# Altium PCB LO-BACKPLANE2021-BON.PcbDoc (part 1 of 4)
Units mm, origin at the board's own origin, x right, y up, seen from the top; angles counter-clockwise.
Board outline 469.9 x 101.6 mm, 4 copper layers (1, Signal Layer 1, Signal Layer 2, 4), stack 1.53 mm thick; 160 components, 92 nets, 524 pads, 8354 vias.
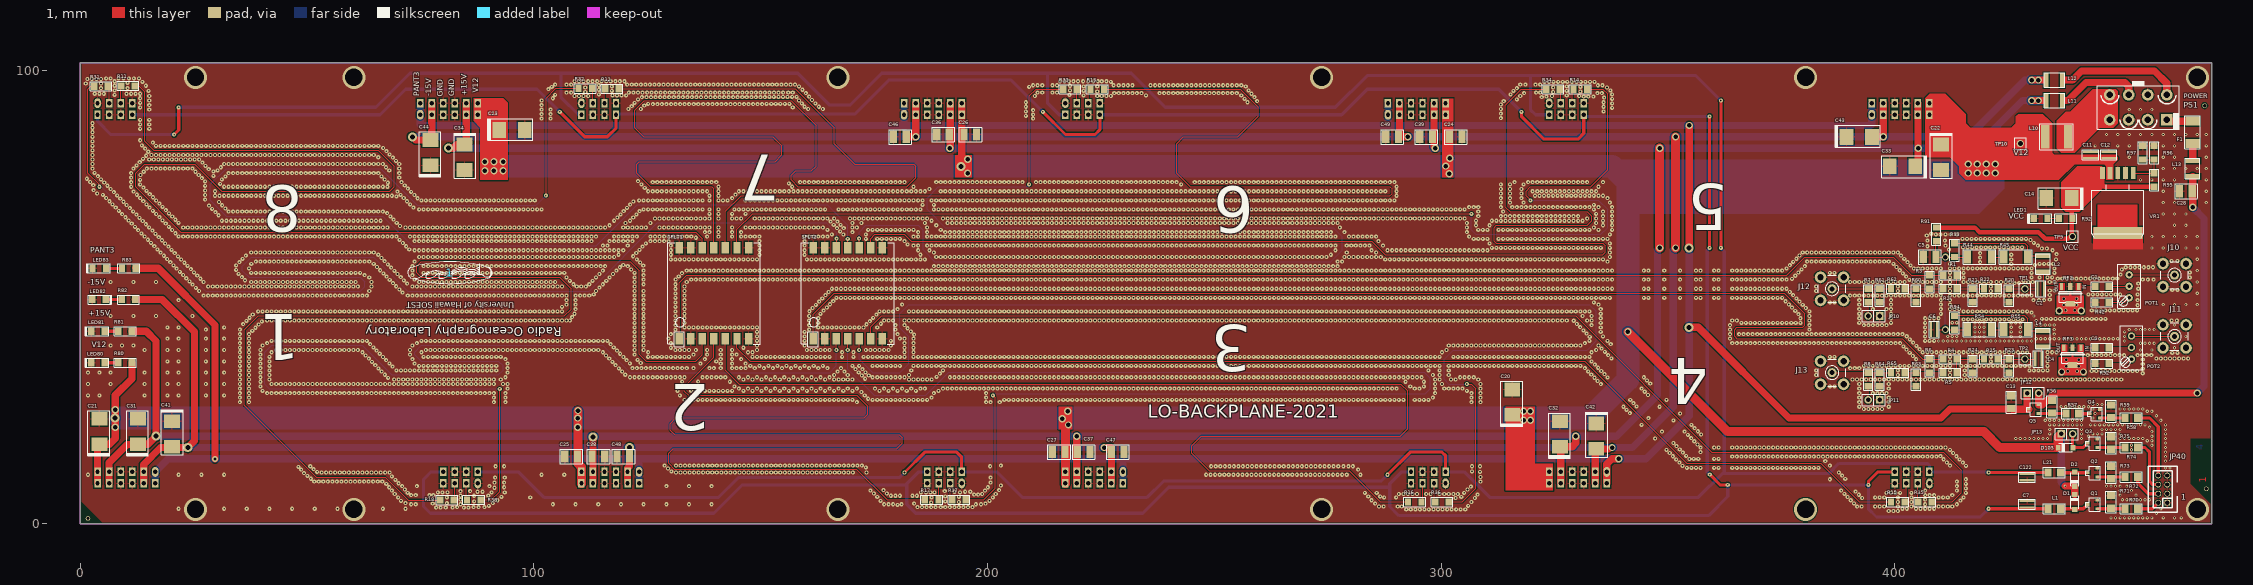
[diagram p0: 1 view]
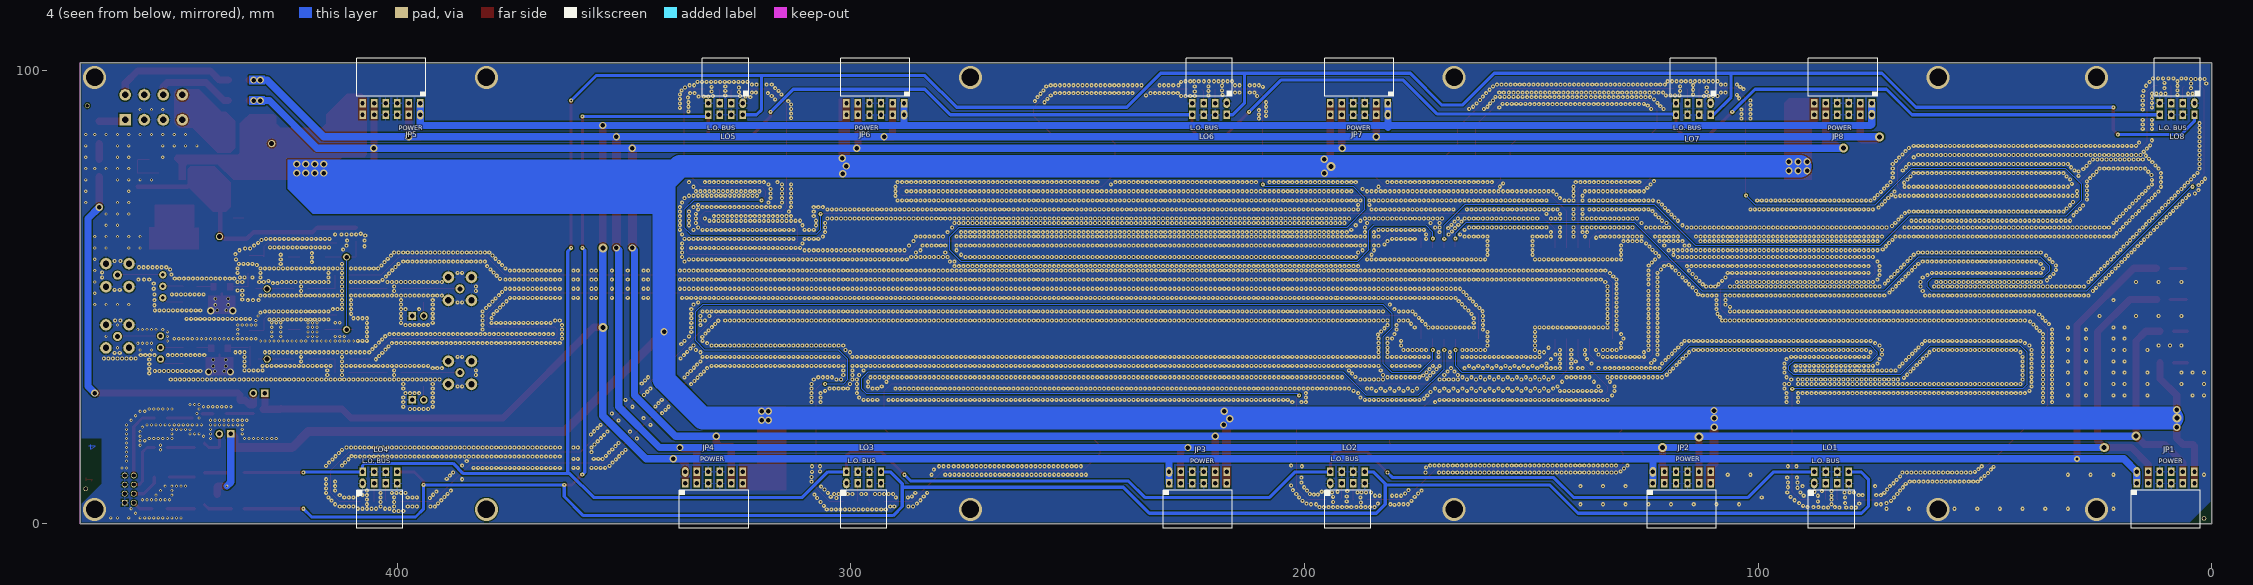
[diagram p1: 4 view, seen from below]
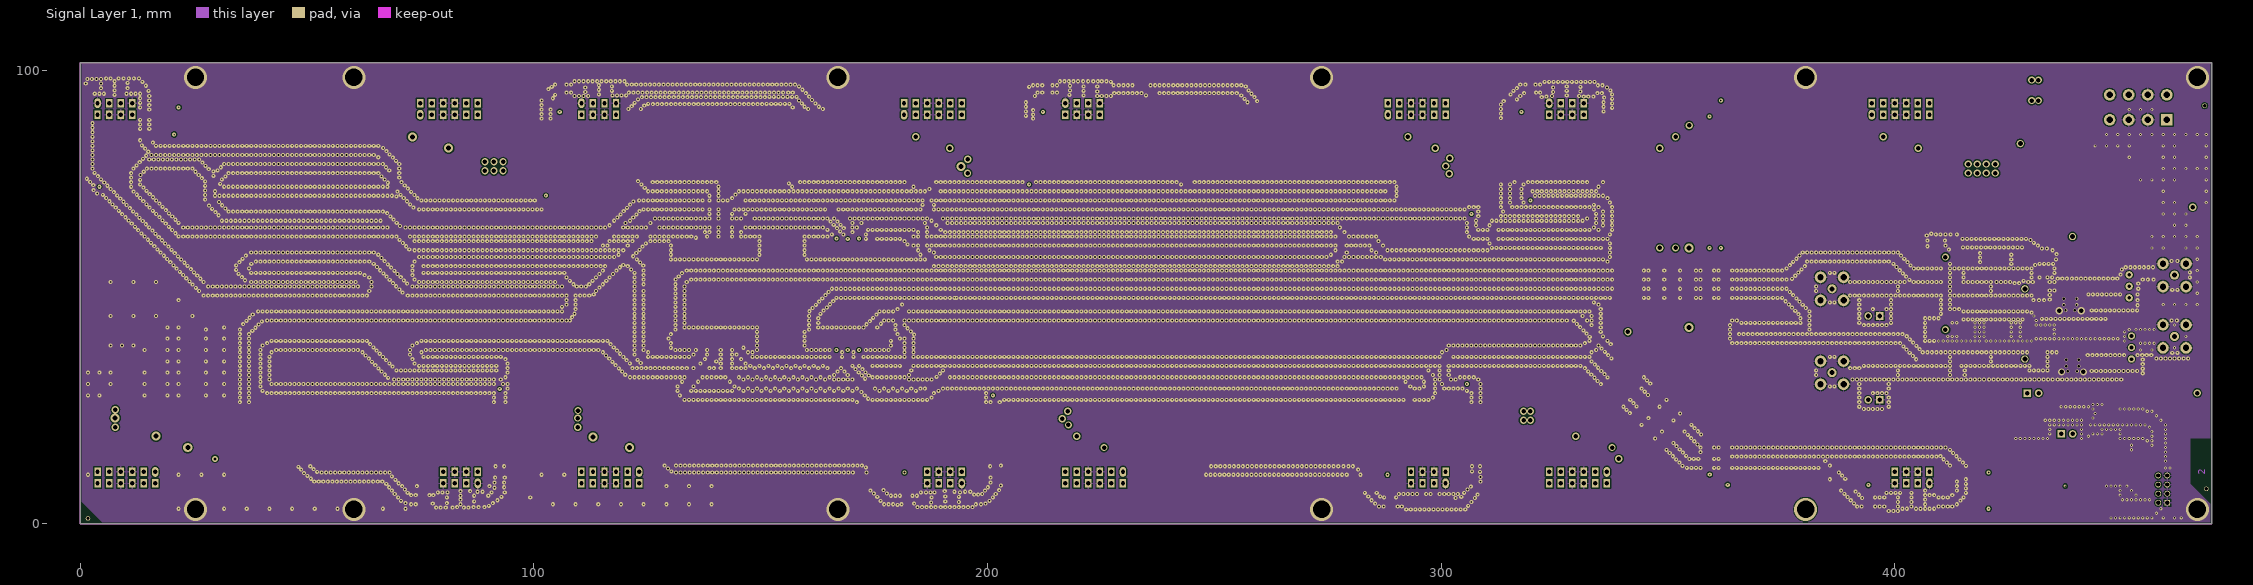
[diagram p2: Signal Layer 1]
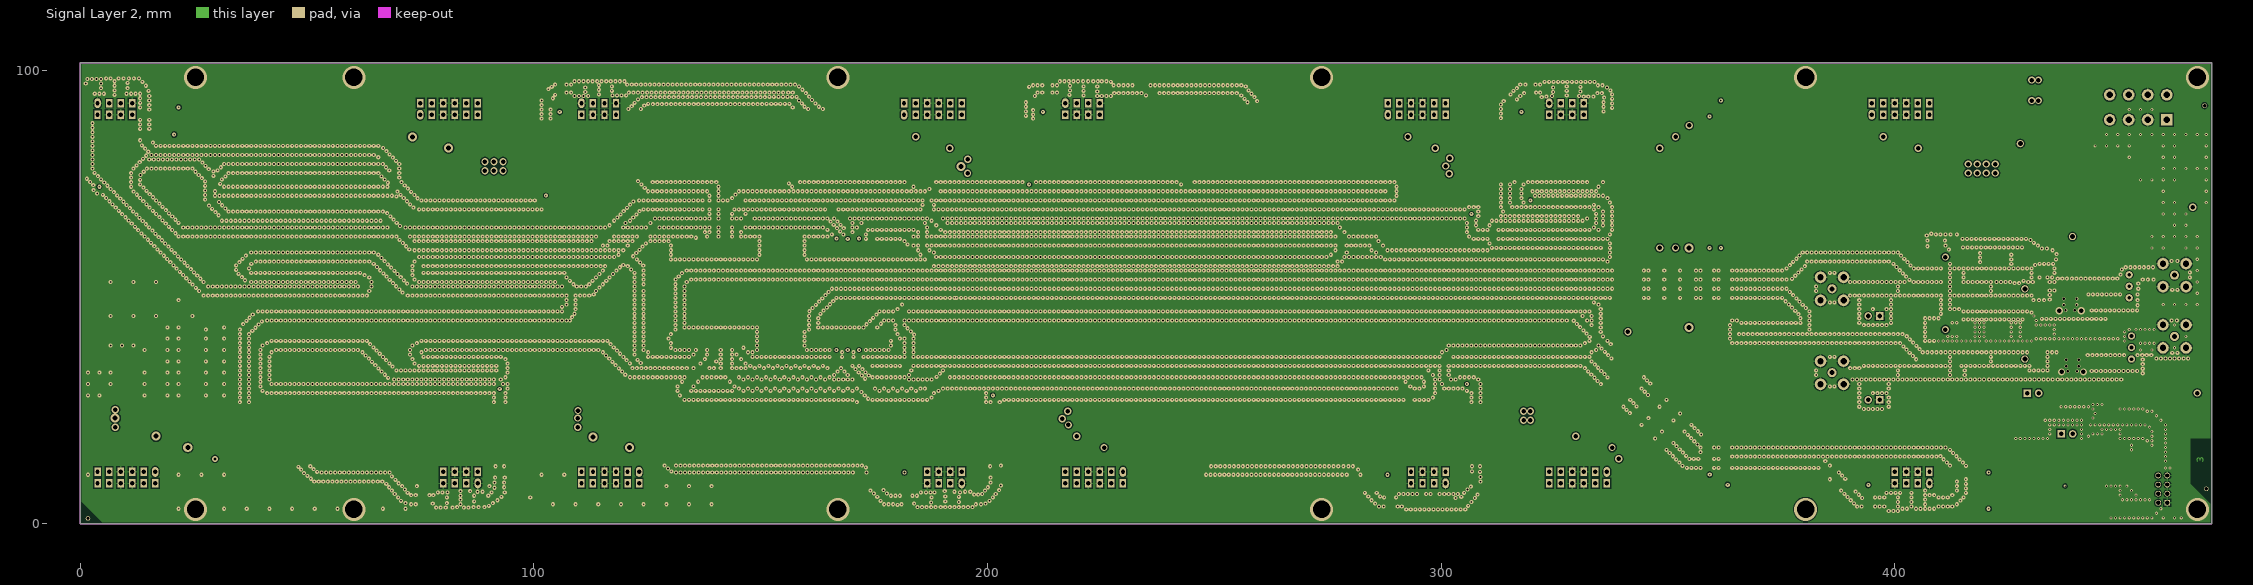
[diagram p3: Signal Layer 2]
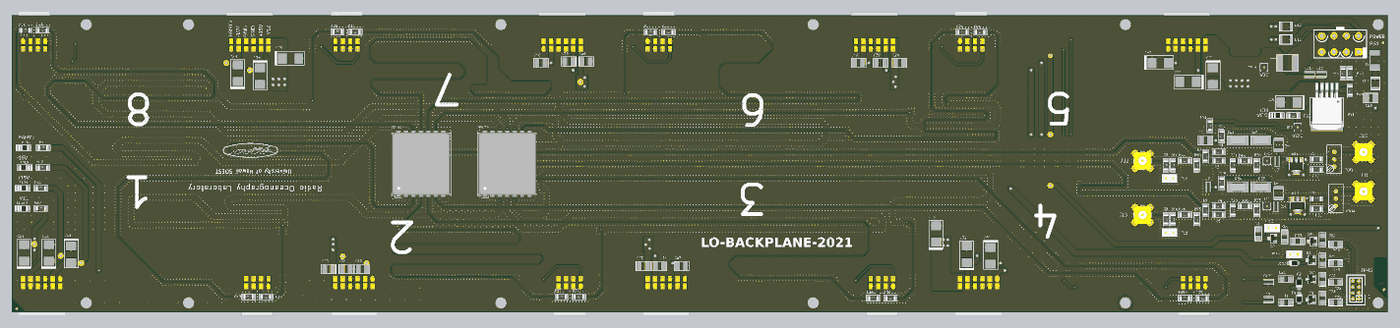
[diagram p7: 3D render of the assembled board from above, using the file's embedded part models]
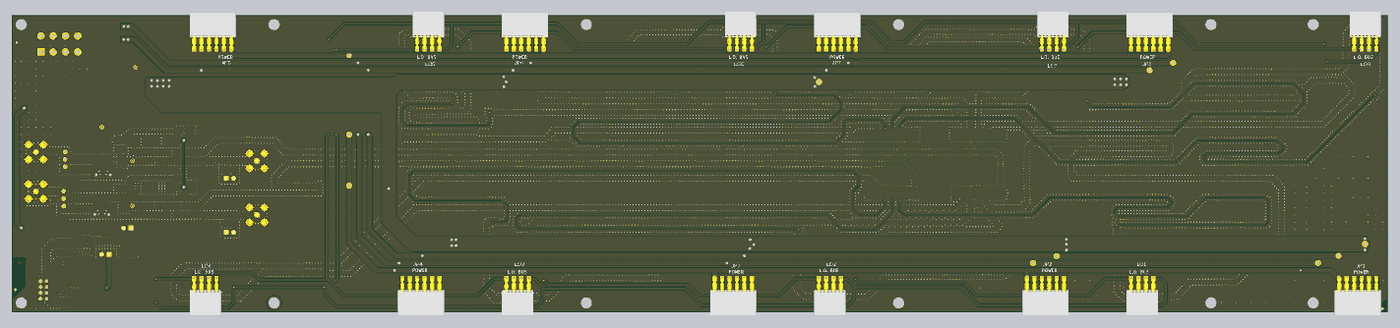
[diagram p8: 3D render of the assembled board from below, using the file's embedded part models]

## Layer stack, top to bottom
Top Solder: solder mask 0.02, Solder Resist, Dk 4
1: signal copper 0.035
Dielectric 1: prepreg 0.13, 2116, Dk 4.45
Signal Layer 1: signal copper 0.035
Dielectric 3: core 1.13, Dk 4.74
Signal Layer 2: signal copper 0.035
Dielectric 2: prepreg 0.13, 2116, Dk 4.45
4: signal copper 0.035
Bottom Solder: solder mask 0.02, Solder Resist, Dk 4

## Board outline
0,0 469.9,0 469.9,101.6 0,101.6

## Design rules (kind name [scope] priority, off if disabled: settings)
Clearance Clearance_6 [InNetClass('50R') vs InNet('GND')] p1: gap=0.18 ignorepadtopadclearanceinfootprint=FALSE
Clearance Clearance_5 [InNetClass('50R') vs InPolygon] p2 off: gap=0.18 ignorepadtopadclearanceinfootprint=FALSE
Clearance Clearance_4 [InNet('RF') vs InPolygon] p3 off: gap=0.55 ignorepadtopadclearanceinfootprint=FALSE
Clearance Clearance_2 [InNet('RF') vs InPolygon] p4 off: gap=0.55 ignorepadtopadclearanceinfootprint=FALSE
Clearance Clearance_3 [InNet('RF') vs InPolygon] p5 off: gap=0.55 ignorepadtopadclearanceinfootprint=FALSE
Clearance Clearance_1 [InPolygon] p6: gap=0.257 ignorepadtopadclearanceinfootprint=FALSE
Clearance [All] p7: gap=0.25 ignorepadtopadclearanceinfootprint=FALSE
ComponentClearance [All] p1 off: gap=0.254 collisioncheckmode=3 verticalgap=0.254 showdistances=FALSE
FabricationTestPointUsage TestPointUsage [All] p1: valid=0 allowmultiple=FALSE
FabricationTestpoint Testpoint [All] p1: side=3 testpointundercomponent=TRUE minsize=1.016 maxsize=2.54 preferedsize=1.524 minholesize=0.508 maxholesize=1.016 preferedholesize=0.813 testpointgrid=0.025 allowsidetop=TRUE allowsidebottom=TRUE usegrid=TRUE gridtolerance=0
HoleSize [All] p1: absolutevalues=TRUE maxlimit=10 minlimit=0.025 maxpercent=80.000 minpercent=20.000
HoleToHoleClearance [All] p1 off: gap=0.01 allowstackedmicrovias=TRUE
Length Length_entrées [InStructureClass('xSignals_entrées')] p1: maxlimit=333.1 minlimit=333
Length Length_sorties [InStructureClass('xSignals_sorties')] p2: maxlimit=274.8 minlimit=274.5
MatchedLengths MatchedLengths_xSignals_entrées [InxSignalClass('Xsignals_entrées')] p1: tolerance=0.2 checknetsindiffpair=FALSE checkdiffpairvsdiffpair=TRUE checkxsignals=TRUE checkothers=TRUE
MatchedLengths MatchedLengths_xSignals_sorties [InxSignalClass('Xsignals_sorties')] p2: tolerance=0.4 checknetsindiffpair=FALSE checkdiffpairvsdiffpair=TRUE checkxsignals=TRUE checkothers=TRUE
PlaneClearance PlaneClearance_15 [HasPad('TP88-TP')] p1 off: clearance=1.27
PlaneClearance PlaneClearance_16 [HasPad('TP85-TP')] p2 off: clearance=1.27
PlaneClearance PlaneClearance_13 [HasPad('TP86-TP')] p3 off: clearance=1.27
PlaneClearance PlaneClearance_14 [HasPad('TP84-TP')] p4 off: clearance=1.27
PlaneClearance PlaneClearance_17 [HasPad('TP81-TP')] p5 off: clearance=1.27
PlaneClearance PlaneClearance_20 [HasPad('TP99-TP')] p6 off: clearance=1.27
PlaneClearance PlaneClearance_21 [HasPad('TP83-TP')] p7 off: clearance=1.27
PlaneClearance PlaneClearance_18 [HasPad('TP87-TP')] p8 off: clearance=1.27
PlaneClearance PlaneClearance_19 [HasPad('TP82-TP')] p9 off: clearance=1.27
PlaneClearance PlaneClearance_4 [HasPad('TPQ3-TP')] p10 off: clearance=0.381
PlaneClearance PlaneClearance_5 [HasPad('TP8-TP')] p11 off: clearance=0.381
PlaneClearance PlaneClearance_6 [HasPad('TP14-TP')] p12 off: clearance=0.381
PlaneClearance PlaneClearance_1 [HasPad('TP3-TP')] p13 off: clearance=0.381
PlaneClearance PlaneClearance_2 [HasPad('TP2-TP')] p14 off: clearance=0.381
PlaneClearance PlaneClearance_3 [HasPad('TP1-TP')] p15 off: clearance=0.381
PlaneClearance PlaneClearance_10 [HasPad('TP5-TP')] p16 off: clearance=0.381
PlaneClearance PlaneClearance_11 [HasPad('TP12-TP')] p17 off: clearance=0.381
PlaneClearance PlaneClearance_12 [HasPad('TP108-TP')] p18 off: clearance=0.381
PlaneClearance PlaneClearance_7 [HasPad('TPQ14-TP')] p19 off: clearance=0.381
PlaneClearance PlaneClearance_8 [HasPad('TP9-TP')] p20 off: clearance=0.381
PlaneClearance PlaneClearance_9 [HasPad('TPQ5-TP')] p21 off: clearance=0.381
PlaneClearance [All] p22 off: clearance=0.254
PlaneConnect PlaneConnect_1 [All] p1 off: planeconnectstyle=Relief reliefexpansion=0.508 reliefentries=4 reliefconductorwidth=0.254 reliefairgap=0.254
PlaneConnect [All] p2 off: planeconnectstyle=Relief reliefexpansion=0.508 reliefentries=4 reliefconductorwidth=0.254 reliefairgap=0.254
PolygonConnect PolygonConnect_1 [IsVia] p1 off: connectstyle=Direct reliefconductorwidth=0.254 reliefentries=4 polygonreliefangle="90 Angle" airgapwidth=0.254
PolygonConnect PolygonConnect_2 [All] p2: thpad.connectstyle=Relief thpad.reliefconductorwidth=0.4 thpad.reliefentries=4 thpad.polygonreliefangle="90 Angle" thpad.airgapwidth=0.257 smdpad.connectstyle=Relief smdpad.reliefconductorwidth=0.4 smdpad.reliefentries=4 smdpad.polygonreliefangle="90 Angle" smdpad.airgapwidth=0.257 via.connectstyle=Direct via.reliefconductorwidth=0.254 via.reliefentries=4 via.polygonreliefangle="90 Angle" via.airgapwidth=0.254
PolygonConnect [All] p3 off: connectstyle=Relief reliefconductorwidth=0.254 reliefentries=4 polygonreliefangle="90 Angle" airgapwidth=0.257
RoutingPriority [All] p1: routingpriority=2
RoutingVias [All] p1: holewidth=0.3 width=0.7 viastyle="Through Hole" minholewidth=0.3 minwidth=0.7 maxholewidth=2 maxwidth=5
SilkToSilkClearance [All] p1 off: silktosilkclearance=0.254
SilkToSolderMaskClearance [IsPad] p1 off: minsilkscreentomaskgap=0.254 clearancetoexposedcopper=TRUE
SolderMaskExpansion [All] p1: expansion=0.051
UnpouredPolygon [All] p1 off:
Width Width_50R [InNetClass('50R')] p1: maxlimit=0.254 minlimit=0.185 preferedwidth=0.254 toplayer_maxwidth=0.185 toplayer_prefwidth=0.185 midlayer1_minwidth=0.254 midlayer2_minwidth=0.254 bottomlayer_maxwidth=0.185 bottomlayer_prefwidth=0.185 minimp=50.000000 maximp=50.000000 favimp=50.000000
Width [All] p2: maxlimit=10 minlimit=0.18 preferedwidth=0.635 midlayer1_minwidth=0.254 midlayer1_maxwidth=0.254 midlayer1_prefwidth=0.254 midlayer2_minwidth=0.254 midlayer2_maxwidth=0.254 midlayer2_prefwidth=0.254 minimp=50.000000 maximp=50.000000 favimp=50.000000
19 further rules are at their usual default settings.

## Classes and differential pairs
component class 1-BON: C11 C12 C14 C20 C21 C22 C23 C24 C25 C26 C27 C28 C31 C32 C33 C34 C36 C37 C38 C39 C41 C42 C43 C44 C46 C47 C48 C49 F1 JP1 JP2 JP3 JP4 JP5 JP6 JP7 JP8 L10 L11 L12 L13 LED1 LED80 LED81 LED82 LED83 PS1 R80 R81 R82 R83 R92 R95 R96 R97 TP9 TP10 VR1
component class 2-BON: AR1 C7 C13 C122 D1 D2 D103 JP12 JP13 JP40 L1 L21 LO1 LO2 LO3 LO4 LO5 LO6 LO7 LO8 Q1 Q2 Q3 Q4 Q5 R56 R57 R58 R59 R70 R71 R72 R73 R74 R75
component class 3-BON: C1 C2 C3 C4 C5 C6 J10 J11 J12 J13 JP10 JP11 L2 L4 POT1 POT2 R1 R2 R3 R4 R5 R6 R7 R8 R11 R12 R13 R14 R15 R16 R17 R18 R20 R21 R22 R23 R24 R25 R31 R32 R33 R34 R35 R36 R37 R38 R42 R44 R45 R52 R54 R55 R60 R61 R62 R63 R64 R65 R91 R93 R94 RF1 RF3 SPLT1 SPLT2 TP1 TP2
net class 50R: I1 I2 I3 I4 I5 I6 I7 I8 I-BUS LOI1+ LOI2 LOI3 LOI4 LOQ1+ LOQ2 LOQ3 LOQ4 NetJ12_1 NetJ13_1 NetJP10_2 NetJP11_2 NetPOT1_1 NetPOT2_1 NetR1_1 NetR1_2 NetR2_2 NetR4_1 NetR4_2 NetR5_2 NetR11_1 NetR12_1 NetR13_1 NetR14_1 NetR15_1 NetR16_1 NetR17_1 NetR18_1 NetR31_1 NetR32_1 NetR33_1 NetR34_1 NetR35_1 NetR36_1 NetR37_1 NetR38_1 Q1 Q2 Q3 Q4 Q5 Q6 Q7 Q8 Q-BUS

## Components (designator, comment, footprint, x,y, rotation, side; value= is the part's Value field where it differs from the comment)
1 "" LOGOTINY 81.495,55.361 r0 top
C1 "22nF NPO" C1206 445.7,52.3 r0 top
C2 "470nF" 0612 432.2,51.8 r90 top
C3 "22nF NPO" C1206 445.7,38.8 r0 top
C4 "470nF" 0612 431.7,36.3 r90 top
C5 "4.7uF" 1210 407.7,58.8 r180 top
C6 "470nF" 0612 408.7,42.8 r270 top
C7 "470nF" 0612 429.2,4.3 r180 top
C11 "470nF" 0612 443.2,81.3 r180 top
C12 "470nF" 0612 447.2,81.3 r180 top
C13 "4.7uF" 1206 425.7,26.8 r90 top
C14 "22uF 20V" 293D 436.2,71.8 r180 top
C20 "22uF 20V" 293D 315.7,26.8 r90 top
C21 "22uF 20V" 293D 4.2,20.3 r90 top
C22 "22uF 20V" 293D 410.2,80.8 r270 top
C23 "22uF 20V" 293D 95.2,86.8 r0 top
C24 "4.7uF" 1210 303.2,85.3 r0 top
C25 "4.7uF" 1210 108.2,14.8 r180 top
C26 "4.7uF" 1210 196.2,85.8 r0 top
C27 "4.7uF" 1210 215.7,15.8 r180 top
C28 "4.7uF" 1210 464.2,73.3 r180 top
C31 "22uF 20V" 293D 12.7,20.3 r90 top
C32 "22uF 20V" 293D 326.2,19.8 r90 top
C33 "22uF 20V" 293D 401.7,78.8 r180 top
C34 "22uF 20V" 293D 84.7,80.8 r270 top
C36 "4.7uF" 1210 190.2,85.8 r180 top
C37 "4.7uF" 1210 221.2,15.8 r0 top
C38 "4.7uF" 1210 114.2,14.8 r0 top
C39 "4.7uF" 1210 296.7,85.3 r180 top
C41 "22uF 20V" 293D 20.2,19.8 r270 top
C42 "22uF 20V" 293D 334.2,19.3 r270 top
C43 "22uF 20V" 293D 392.2,85.3 r0 top
C44 "22uF 20V" 293D 77.2,81.8 r90 top
C46 "4.7uF" 1210 180.7,85.3 r0 top
C47 "4.7uF" 1210 228.7,15.8 r180 top
C48 "4.7uF" 1210 119.7,14.8 r0 top
C49 "4.7uF" 1210 289.2,85.3 r0 top
C122 "470nF" 0612 429.2,10.3 r0 top
D1 "1N4148W" SOD123 439.7,4.8 r90 top
D2 "1N4148W" SOD123 439.7,9.8 r270 top
D103 "1N4148W" SOD123 437.7,16.8 r180 top
F1 "3A" "0452 (Littlefuse)" 465.7,86.3 r90 top
J10 "LO-I" MCX-J-P-H-ST-TH1 461.7,54.8 r0 top
J11 "LO-Q" MCX-J-P-H-ST-TH1 461.7,41.3 r0 top
J12 "LO-I" MCX-J-P-H-ST-TH1 386.2,51.8 r0 top
J13 "LO-Q" MCX-J-P-H-ST-TH1 386.2,33.3 r0 top
JP1 "POWER" SSW-106-02-G-D-RA 16.51,11.43 r0 bottom
JP2 "POWER" SSW-106-02-G-D-RA 123.19,11.43 r0 bottom
JP3 "POWER" SSW-106-02-G-D-RA 229.87,11.43 r0 bottom
JP4 "POWER" SSW-106-02-G-D-RA 336.55,11.43 r0 bottom
JP5 "POWER" SSW-106-02-G-D-RA 394.97,90.17 r180 bottom
JP6 "POWER" SSW-106-02-G-D-RA 288.29,90.17 r180 bottom
JP7 "POWER" SSW-106-02-G-D-RA 181.61,90.17 r180 bottom
JP8 "POWER" SSW-106-02-G-D-RA 74.93,90.17 r180 bottom
JP10 "" 2X2.54 396.7,45.8 r270 top
JP11 "" 2X2.54 396.7,27.3 r270 top
JP12 "" 2X2.54 429.2,28.8 r90 top
JP13 "" 2X2.54 436.7,19.8 r90 top
JP40 "RX ATTEN. CTRL" 2MM4X2SHRD 459.105,7.62 r90 top
L1 "Ferrite 1206" 1206 435.2,3.3 r0 top
L2 "4.7uH 1812" 1812 432.7,57.3 r90 top
L4 "4.7uH 1812" 1812 432.7,40.8 r90 top
L10 "Ferrite 2220" 2220 435.7,85.3 r0 top
L11 "Ferrite 1812" 1812 435.2,93.3 r0 top
L12 "Ferrite 1812" 1812 435.2,97.8 r0 top
L13 "Ferrite 1812" 1812 465.7,78.3 r90 top
L21 "Ferrite 1206" 1206 435.2,11.3 r0 top
LED1 "LO POWER" 1206D1 433.7,67.3 r180 top
LED80 "GALI-POWER" 1206D1 5.386,35.498 r180 top
LED81 "VA15+" 1206D1 5.386,42.428 r180 top
LED82 "VA15-" 1206D1 2.631,49.411 r0 top
LED83 "ACT-ANT" 1206D1 5.7,56.3 r180 top
LO1 "L.O. BUS" SSW-104-02-G-D-RA#1 87.63,11.43 r180 bottom
LO2 "L.O. BUS" SSW-104-02-G-D-RA#1 194.31,11.43 r180 bottom
LO3 "L.O. BUS" SSW-104-02-G-D-RA#1 300.99,11.43 r180 bottom
LO4 "L.O. BUS" SSW-104-02-G-D-RA#1 407.67,11.43 r180 bottom
LO5 "L.O. BUS" SSW-104-02-G-D-RA#1 323.85,90.17 r0 bottom
LO6 "L.O. BUS" SSW-104-02-G-D-RA#1 217.17,90.17 r0 bottom
LO7 "L.O. BUS" SSW-104-02-G-D-RA#1 110.49,90.17 r0 bottom
LO8 "L.O. BUS" SSW-104-02-G-D-RA#2 3.81,90.17 r0 bottom
POT1 "POT 50" t93ya 451.7,49.8 r90 top locked
POT2 "POT 50" t93ya 452.2,36.3 r90 top locked
PS1 "POWER" MFTJR2X4 453.7,91.8 r180 top
Q1 "MMBT2484LT1G" SOT23 444.7,3.3 r270 top
Q2 "MMBT2484LT1G" SOT23 444.7,10.3 r270 top
Q3 "MMBT2484LT1G" SOT23 444.7,16.8 r270 top
Q4 "MMBT2484LT1G" SOT23 445.2,23.3 r270 top
Q5 "PMV48XP,215" SOT23 431.7,24.3 r270 top
R1 "49.9" R1206 412.2,54.8 r180 top
R2 "49.9" R1206 412.2,51.8 r180 top
R3 "49.9" R1206 407.7,53.3 r270 top
R4 "49.9" R1206 412.2,36.3 r180 top
R5 "49.9" R1206 412.2,33.3 r180 top
R6 "49.9" R1206 407.7,34.8 r270 top
R7 "49.9" R1206 394.2,50.3 r270 top
R8 "49.9" R1206 394.2,31.8 r270 top
R11 "0" R1206 10.504,96.527 r180 top
R12 "0" R1206 117.244,95.881 r180 top
R13 "0" R1206 224.2,95.8 r180 top
R14 "0" R1206 330.7,95.8 r180 top
R15 "0" R1206 400.7,4.8 r0 top
R16 "0" R1206 294.2,4.8 r0 top
R17 "0" R1206 187.7,5.3 r0 top
R18 "0" R1206 80.869,5.23 r0 top
R20 "124" R1206 425.2,50.3 r270 top
R21 "124" R1206 417.2,50.3 r270 top
R22 "48.7" R1206 421.2,51.8 r180 top
R23 "124" R1206 425.2,34.8 r270 top
R24 "124" R1206 417.2,34.8 r270 top
R25 "48.7" R1206 421.2,36.3 r180 top
R31 "0" R1206 4.545,96.428 r0 top
R32 "0" R1206 111.335,95.956 r0 top
R33 "0" R1206 218.2,95.8 r0 top
R34 "0" R1206 324.7,95.8 r0 top
R35 "0" R1206 406.7,4.8 r180 top
R36 "0" R1206 300.2,4.8 r180 top
R37 "0" R1206 193.7,5.3 r180 top
R38 "0" R1206 86.754,5.255 r180 top
R42 "105" R1206 445.7,48.8 r180 top
R44 "20.5ohm" 2010-5x2.5 418.7,58.8 r0 top
R45 "20.5ohm" 2010-5x2.5 426.7,58.8 r0 top
R52 "105" R1206 445.7,35.3 r180 top
R54 "20.5ohm" 2010-5x2.5 418.7,42.8 r0 top
R55 "20.5ohm" 2010-5x2.5 426.7,42.8 r0 top
R56 "10k" 1206 434.7,25.8 r270 top
R57 "2K" 1206 439.2,24.3 r0 top
R58 "1k" 1206 452.2,23.3 r180 top
R59 "10k" 1206 447.7,24.8 r90 top
R60 "124" R1206 404.7,50.3 r270 top
R61 "124" R1206 396.7,50.3 r270 top
R62 "48.7" R1206 400.7,51.8 r180 top
R63 "124" R1206 404.7,31.8 r270 top
R64 "124" R1206 396.7,31.8 r270 top
R65 "48.7" R1206 400.7,33.3 r180 top
R70 "1k" 1206 452.2,3.3 r0 top
R71 "10k" 1206 447.7,4.8 r90 top
R72 "1k" 1206 452.2,10.3 r180 top
R73 "10k" 1206 447.7,11.3 r90 top
R74 "1k" 1206 452.2,16.8 r180 top
R75 "10k" 1206 447.7,17.8 r90 top
R80 "4.49k" R1206 9.886,35.498 r0 top
R81 "4.49k" R1206 9.886,42.428 r0 top
R82 "4.49k" R1206 10.631,49.411 r0 top
R83 "4.49k" R1206 10.7,56.3 r0 top
R91 "1R0" R1206 409.2,63.8 r270 top
R92 "4.49k" R1206 437.7,67.3 r180 top
R93 "0 DNI" R1206 413.2,60.3 r90 top
R94 "0 DNI" R1206 413.2,44.3 r90 top
R95 "1.8K" R1206 457.2,75.8 r90 top
R96 "249" R1206 457.2,81.8 r90 top
R97 "DNI" R1206 454.7,81.8 r90 top
RF1 "GALI-84" DF782 438.7,52.3 r180 top
RF3 "GALI-84" DF782 439.2,38.8 r180 top
SPLT1 "JCPS-8-10+" BG291 139.7,50.8 r0 top locked
SPLT2 "JCPS-8-10+" BG291 169.2,50.8 r0 top locked
TP1 "I-BUS" 61300111121 428.7,51.8 r0 top
TP2 "Q-BUS" 61300111121 428.7,36.3 r0 top
TP9 "+10.4V" 61300111121 439.2,63.3 r0 top
TP10 "+12V" 61300111121 427.7,83.8 r90 top
VR1 "LM2941S" TO263-5 449.2,77.3 r180 top

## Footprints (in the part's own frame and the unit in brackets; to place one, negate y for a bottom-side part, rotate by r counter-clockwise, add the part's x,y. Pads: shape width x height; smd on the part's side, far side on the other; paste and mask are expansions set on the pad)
2MM4X2SHRD [mm]
  rect 1.27x1.27 hole 0.914: 1(-3,-1)
  round 1.27 hole 0.914: 2(-3,1) 3(-1,-1) 4(-1,1) 5(1,-1) 6(1,1) 7(3,-1) 8(3,1)
  silkscreen extent -5.08,-3.18 5.08,3.18
2X2.54 [mm]
  rect 1.67x1.67 hole 1: 1(0,0)
  round 1.67 hole 1: 2(0,-2.54)
  silkscreen extent -1.27,-3.81 1.27,1.27, body extent -1.26,-3.8 1.28,1.28, height 9.54
293D [mm]
  rect 3x3.5 smd: +(-2.806,0) -(2.806,0)
  silkscreen extent -5.32,-2.3 4.59,2.51, body extent -3.69,-2.19 3.71,2.26, height 3.01
"0452 (Littlefuse)" [mm]
  rect 1.96x3.15 smd mask+0.05: 1(-2.45,0) 2(2.45,0)
  silkscreen extent -3.6,-1.7 3.6,1.7, body extent -3,-1.34 3,1.35, height 2.69
0612 [mm]
  rect 3.3x0.5 smd mask+0.1: 1(0,0.7) 2(0,-0.7)
  silkscreen extent -1.8,-1.1 1.8,1.1, body extent -1.6,-0.8 1.6,0.8, height 0.6
1206 [mm] "Chip Resistor; Body 3.2 x 1.6 mm (LxW typ)"
  rect 1.6x1.8 smd: 1(-1.4,0) 2(1.4,0)
  silkscreen extent -2.41,-1.14 2.41,1.14
1206D1 [mm]
  rect 1.4x1.6 smd: A(0,0) K(3,0)
  silkscreen extent -0.9,-1 4.32,1, body extent 0,-0.86 3.35,0.86, height 0.85
1210 [mm] "Chip Capacitor; Body 3.2 x 2.5 mm (LxW typ)"
  rect 1.6x2.7 smd: 1(-1.4,0) 2(1.4,0)
  silkscreen extent -2.5,-1.6 2.5,1.6
1812 [mm] "Chip Capacitor; Body 4.5 x 3.2 mm (LxW typ)"
  rect 1x3.2 smd: 1(-1.75,0) 2(1.75,0)
  silkscreen extent -2.25,-1.6 2.25,1.6
2010-5x2.5 [mm]
  rect 1.65x2.85 smd mask+0.1: 1(-2.65,0) 2(2.65,0)
  silkscreen extent -3.6,-1.6 3.6,1.6, body extent -2.5,-1.25 2.5,1.25, height 0.6
2220 [mm] "Chip Resistor; Body 5.7 x 5 mm (LxW typ)"
  rect 1.85x5.2 smd: 1(-2.525,0) 2(2.525,0)
  silkscreen extent -3.7,-2.85 3.7,2.85
61300111121 [mm] "1pins, 1 row, straight, gold plating"
  round 1.6 hole 1.1: 1(0,0)
  silkscreen extent -1.27,-1.27 1.27,1.27, body extent -1.27,-1.27 1.27,1.27, height 8.57
BG291 [mm]
  rect 1.65x2.54 smd mask+0.1: 1(-7.62,-10.035) 2(-5.08,-10.035) 3(-2.54,-10.035) 4(0,-10.035) 5(2.54,-10.035) 6(5.08,-10.035) 7(7.62,-10.035) 8(7.62,10.035) 9(5.08,10.035) 10(2.54,10.035) 11(0,10.035) 12(-2.54,10.035) 13(-5.08,10.035) 14(-7.62,10.035)
  silkscreen extent -10.2,-11.8 10.2,11.2, body extent -10.16,-11.15 10.16,11.15, height 6.45
C1206 [mm]
  rect 1.4x1.6 smd mask+0.05: 1(-1.5,0) 2(1.5,0)
  silkscreen extent -2.4,-1 2.4,1, body extent -1.6,-0.8 1.6,0.8, height 1
DF782 [mil]
  rect 28x60 smd: 1(-75,0) 3(75,0)
  rect 36x60 smd: 2(0,0)
  rect 85x50 smd: 4(0,150)
  1 region: 120,240 -120,240 -120,80 120,80
  1 region: 100,35 45,35 45,-30 100,-30
  1 region: -45,35 -100,35 -100,-30 -45,-30
  1 region: 10,115 -10,115 -10,50 10,50
  silkscreen extent -100,40 100,135, body extent -91,-2 91,165, height 63
LOGOTINY [mm]
  silkscreen extent -9.29,-2.41 9.29,2.41
MCX-J-P-H-ST-TH1 [mm]
  round 2 hole 1.1 mask+0.2: 1(0,0)
  round 2.54 hole 1.4 mask+0.2: 2(-2.54,2.54) 3(-2.54,-2.54) 4(2.54,2.54) 5(2.54,-2.54)
  silkscreen extent -3,-3 3,3, body extent -3,-3 3,3, height 5.81
MFTJR2X4 [mm]
  rect 2.54x2.54 hole 1.422: 1(-6.3,2.75)
  round 2.54 hole 1.422: 2(-2.1,2.75) 3(2.1,2.75) 4(6.3,2.75) 5(-6.3,-2.75) 6(-2.1,-2.75) 7(2.1,-2.75) 8(6.3,-2.75)
  silkscreen extent -9.05,-5.8 9,4.85
R1206 [mm]
  rect 1.4x1.6 smd mask+0.05: 1(-1.5,0) 2(1.5,0)
  silkscreen extent -2.4,-1 2.4,1, body extent -1.6,-0.8 1.6,0.8, height 1
SOD123 [mm]
  rect 1.1x1.22 smd: A(-1.635,0) K(1.635,0)
  silkscreen extent -1.4,-0.9 1.4,0.9, body extent -1.85,-0.81 1.85,0.79, height 1.27
SOT23 [mm]
  rect 0.6x0.8 smd: 1(0,0) 2(-1.905,0) 3(-0.952,-2.159)
  silkscreen extent -2.42,-2.7 0.58,0.6, body extent -2.42,-2.48 0.48,0.32, height 1.3
SSW-104-02-G-D-RA#1 [mil]
  oval 56x85 hole 38: 1(0,-100)
  rect 56x75 hole 38: 2(0,0) 3(100,-100) 4(100,0) 5(200,-100) 6(200,0) 7(300,-100) 8(300,0)
  silkscreen extent -50,-490 350,-160, body extent -60,-496 360,7, height 192
SSW-104-02-G-D-RA#2 [mil]
  oval 56x85 hole 38: 1(0,-100)
  rect 55.12x75 hole 38: 2(0,0) 4(100,0)
  rect 56x75 hole 38: 3(100,-100) 5(200,-100) 6(200,0) 7(300,-100) 8(300,0)
  silkscreen extent -50,-490 350,-160, body extent -60,-496 360,7, height 192
SSW-106-02-G-D-RA [mil]
  oval 56x85 hole 38: 1(0,0)
  rect 56x75 hole 38: 2(0,100) 3(-100,0) 4(-100,100) 5(-200,0) 6(-200,100) 7(-300,0) 8(-300,100) 9(-400,0) 10(-400,100) 11(-500,0) 12(-500,100)
  silkscreen extent -550,160 50,490, body extent -560,-13 60,490, height 192
t93ya [mm] "Potentiomètre série T93YA"
  round 1.6 hole 0.8: 1(0,0) 2(2.54,0) 3(5.08,0)
  silkscreen extent -2.31,-2.5 7.39,2.5
TO263-5 [mil]
  rect 42x102.36 smd: 1(-134,0) 2(-67,0) 3(0,0) 4(67,0) 5(134,0)
  rect 425x102.36 smd: 6(0,520)
  1 region: -215,600 -215,470 -170,470 -170,275 175,275 175,475 215,475 215,600
  silkscreen extent -225,100 225,558, body extent -195,-33 199,583, height 188

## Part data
C1 C3: library part CAP, MFR=Murata, MFR PART=GRM3195C1H223JA01D
C2 C4 C6 C7 C11 C12 C122: library part CAP, MFR=TDK, MFR PART=C1632X7R1E474M115AC
C5: library part C1206, MFR=TDK, MFR PART=C3225X7R1E475K200AA
C13: library part C1206, MFR="Taiyo Yuden"
C14 C20 C21 C22 C23 C31 C32 C33 C34 C41 C42 C43 C44: library part "CAPACITOR POL", MFR=Kemet, MFR PART=T495D226M020ATE225
C24 C25 C26 C27 C28 C36 C37 C38 C39 C46 C47 C48 C49: library part C1206, MFR="TDK Corporation", MFR PART=C3225X7R1E475K200AA
D1 D2 D103: library part DIODE2, MFR="Micro Commercial", MFR PART=1N4148W-TP
F1: library part FUSE1, "Fuse"
J10 J11 J12 J13: library part SMA-4G, MFR="TE Connectivity AMP Connectors", MFR PART=5-1814832-1
JP1 JP2 JP3 JP4 JP5 JP6 JP7 JP8: library part "HEADER 6X2", MFR="Samtec Inc.", MFR PART=SSW-106-02-G-D-RA
JP10 JP11 JP12 JP13: library part STRAP
JP40: library part "HEADER 4X2_1", MFR=3M, MFR PART=159208-6012
L1 L21: library part IND, MFR="Taiyo Yuden", MFR PART=HZ1206D102R-10
L2 L4: library part IND, MFR="API Delevan", MFR PART=S1812R-472K
L10: library part IND, MFR=Laird, MFR PART=HR2220V801R-10
L11 L12: library part IND, MFR="Taiyo Yuden", MFR PART=FBMH4532HM132-T
L13: library part IND, MFR=Laird, MFR PART=HI1812V101R-10
LED1: library part LED_1, MFR=Kingbright, MFR PART=APTL3216CGCK
LED80: library part LED_0, MFR=Kingbright, MFR PART=APTD3216SURCK
LED81: library part LED_0, MFR=Kingbright, MFR PART=APTD3216SECK
LED82: library part LED_0, MFR=Kingbright, MFR PART=APTD3216SYCK
LED83: library part LED_0, MFR=Kingbright, MFR PART=APTD3216QBC/D
LO1 LO2 LO3 LO4 LO5 LO6 LO7 LO8: library part "HEADER 4X2", MFR=Samtec, MFR PART=SSW-104-02-G-D-RA
POT1 POT2: library part POT, MFR="Vishay Sfernice", MFR PART=T93YA500KT20
PS1: library part "HEADER 4X2_0", MFR="M olex", MFR PART=0039281083
Q1 Q2 Q3 Q4: library part NPN_0
Q5: library part "MOSFET P_0"
R1 R2 R3 R4 R5 R6 R7 R8 R11 R12 R13 R14 R15 R16 R17 R18 R20 R21 R22 R23 R24 R25 R31 R32 R33 R34 R35 R36 R37 R38 R42 R52 R60 R61 R62 R63 R64 R65: library part RES, MFR=Yageo, MFR PART=RC1206FR-07105RL
R44 R45 R54 R55: library part R1206, MFR="Vishay Dale", MFR PART=CRCW201020R5FKEF
R56 R57: library part RES1206, MFR=Yageo
R58 R59 R70 R71 R72 R73 R74 R75: library part RES1206_Dup1, MFR=Yageo
R80 R81 R82 R83: library part RESISTOR, MFR=Yageo, MFR PART=RC1206FR-072K49L
R91: library part RES1206, MFR=Yageo, MFR PART=RC1206FR-071RL
R92: library part RES1206, MFR=Yageo, MFR PART=RC1206FR-072K49L
R93 R94: library part R1206, MFR="Vishay Dale"
R95: library part RESISTOR, MFR=Yageo, MFR PART=RC1206FR-071K8L
R96: library part RESISTOR, MFR=Yageo, MFR PART=RC1206FR-07249RL
R97: library part RESISTOR, MFR PART=ns
RF1 RF3: library part GVA-84, MFR=MiniCircuits
TP1 TP2: library part TP, MFR PART=ns
TP9: library part TP_0, MFR PART=ns
TP10: library part TP_0
VR1: library part LM7805_0, MFR=TI, MFR PART=LM2941SX

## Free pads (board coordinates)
  round 1 hole 0.762: mire(1.7,1.175) mire(468.325,92.175) mire(468.7,7.675)
  round 2 on Mech16 mask+0.2: X(3.81,90.17) X(16.51,11.43) X(74.93,90.17) X(87.63,11.43) X(110.49,90.17) X(123.19,11.43) X(181.61,90.17) X(194.31,11.43) X(217.17,90.17) X(229.87,11.43) X(288.29,90.17) X(300.99,11.43) X(323.85,90.17) X(336.55,11.43) X(394.97,90.17) X(407.67,11.43)

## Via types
v1: diameter 0.9, hole 0.35, 1 to 4, 7972 vias
v2: diameter 0.7, hole 0.3, 1 to 4, 287 vias
v3: diameter 1.6, hole 1, 1 to 4, 60 vias
v4: diameter 0.762, hole 0.508, 1 to 4, 12 vias
v5: diameter 5.08, hole 3.85, 1 to 4, 12 vias
v6: diameter 2, hole 1.1, 1 to 4, 10 vias
v7: diameter 1.27, hole 0.7, 1 to 4, 1 vias

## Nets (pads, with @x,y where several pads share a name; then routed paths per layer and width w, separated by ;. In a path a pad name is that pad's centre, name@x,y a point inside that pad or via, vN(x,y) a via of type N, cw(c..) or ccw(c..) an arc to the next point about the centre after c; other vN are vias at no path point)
+15VBUS: C31.+ C32.+ C33.+ C34.+ C36.1 C37.1 C38.1 C39.1 JP1.9 JP1.10 JP2.9 JP2.10 JP3.9 JP3.10 JP4.9 JP4.10 JP5.9 JP5.10 JP6.9 JP6.10 JP7.9 JP7.10 JP8.9 JP8.10 L11.1 R81.2 | length 871.6
  1 w1.6: JP1.10@6.35,8.89 JP1.9@6.35,11.43 6.35,13.45 10.394,17.494 C31.+@12.7,17.494 14.894,17.494 v6(16.7,19.3) 16.7,40.3 14.572,42.428 R81.2@11.386,42.428 ; v6(81.2,82.8) 82.2,82.8 83.006,83.606 85.2,83.606 85.09,83.716 JP8.9@85.09,90.17 JP8.10@85.09,92.71 ; JP2.10@113.03,8.89 JP2.9@113.03,11.43 v6(113.03,19.13) ; v3(191.7,82.8) 191.77,82.87 JP7.9@191.77,90.17 JP7.10@191.77,92.71 ; v3(219.7,19.3) 219.71,19.29 JP3.9@219.71,11.43 JP3.10@219.71,8.89 ; JP6.10@298.45,92.71 JP6.9@298.45,90.17 298.45,83.05 v3(298.7,82.8) ; JP4.10@326.39,8.89 JP4.9@326.39,11.43 326.39,16.804 C32.+@326.2,16.994 328.894,16.994 329.7,17.8 v3(329.7,19.3) ; C33.+@404.506,78.8 405.13,79.424 JP5.9@405.13,90.17 JP5.10@405.13,92.71 ; v3(430.2,93.3) v3(431.7,93.3) 432.7,93.3
  1 w2: v3(348.2,60.8) v3(348.2,82.8)
  4 w1.6: v6(16.7,19.3) v3(219.7,19.3) v3(329.7,19.3) 338.7,19.3 347.7,28.3 347.7,60.3 v3(348.2,60.8) ; v6(81.2,82.8) v3(191.7,82.8) v3(298.7,82.8) v3(348.2,82.8) v3(405.2,82.8) 417.7,82.8 428.2,93.3 v3(430.2,93.3)
-15VBUS: C41.- C42.- C43.- C44.- C46.2 C47.2 C48.2 C49.2 JP1.3 JP1.4 JP2.3 JP2.4 JP3.3 JP3.4 JP4.3 JP4.4 JP5.3 JP5.4 JP6.3 JP6.4 JP7.3 JP7.4 JP8.3 JP8.4 L12.1 R82.2 | length 882.7
  1 w1.6: R82.2@12.131,49.411 18.089,49.411 25.2,42.3 25.2,18.3 v6(23.7,16.8) 17.7,16.8 13.97,13.07 JP1.3@13.97,11.43 JP1.4@13.97,8.89 ; v6(73.2,85.3) 73.894,84.606 C44.-@77.2,84.606 77.47,84.876 JP8.3@77.47,90.17 JP8.4@77.47,92.71 ; JP2.4@120.65,8.89 JP2.3@120.65,11.43 120.65,12.25 121.1,12.7 C48.2@121.1,14.8 v6(121.1,16.8) ; C46.2@182.1,85.3 v3(184.2,85.3) 184.2,92.66 JP7.4@184.15,92.71 ; v3(225.7,16.8) 227.2,16.8 227.3,16.7 C47.2@227.3,15.8 227.33,15.77 JP3.3@227.33,11.43 JP3.4@227.33,8.89 ; JP6.4@290.83,92.71 JP6.3@290.83,90.17 290.83,85.53 C49.2@290.6,85.3 v3(292.7,85.3) ; JP4.4@334.01,8.89 JP4.3@334.01,11.43 334.01,16.304 C42.-@334.2,16.494 336.894,16.494 ; C43.-@395.006,85.3 v3(397.51,85.3) JP5.3@397.51,90.17 JP5.4@397.51,92.71 ; v3(430.2,97.8) v3(431.7,97.8) 432.7,97.8
  1 w2: v3(351.7,60.8) v3(351.7,85.3)
  4 w1.6: v6(23.7,16.8) v6(121.1,16.8) v3(225.7,16.8) v3(337.7,16.8) 342.2,16.8 351.2,25.8 351.2,60.3 v3(351.7,60.8) ; v6(73.2,85.3) v3(184.2,85.3) v3(292.7,85.3) v3(351.7,85.3) v3(397.51,85.3) 416.2,85.3 428.7,97.8 v3(430.2,97.8)
ANT_ON: JP40.8 R58.1 | length 16.1
  1 w0.7: R58.1@453.6,23.3 456.2,23.3 458.105,21.395 JP40.8@458.105,10.62
ATTEN: C122.1 L21.1 LO1.2 LO2.2 LO3.2 LO4.2 LO5.2 LO6.2 LO7.2 LO8.2 | length 874.4
  1 w0.7: v1(20.7,85.8) 21.7,86.8 v1(21.7,91.8) ; v1(181.7,11.3) 186.2,15.8 193.2,15.8 194.31,14.69 LO2.2@194.31,11.43 ; v1(288.2,10.8) 293.2,15.8 300.2,15.8 300.99,15.01 LO3.2@300.99,11.43 ; v1(361.7,60.8) v1(361.7,93.3) ; v1(420.7,11.3) L21.1@433.8,11.3
  4 w0.7: LO8.2@3.81,90.17 3.81,88.69 6.7,85.8 v1(20.7,85.8) ; v1(21.7,91.8) 65.2,91.8 72.7,99.3 105.95,99.3 ; LO1.2@87.63,11.43 96.57,11.43 102.2,5.8 140.7,5.8 145.075,10.175 180.575,10.175 v1(181.7,11.3) ; LO7.2@110.49,90.17 109.83,90.17 105.95,94.05 105.95,99.3 ; LO2.2@194.31,11.43 202.07,11.43 207.7,5.8 235.2,5.8 238.825,9.425 286.825,9.425 v1(288.2,10.8) ; LO6.2@217.17,90.17 215.83,90.17 213.2,92.8 213.2,99.3 ; LO3.2@300.99,11.43 305.07,11.43 310.7,5.8 356.7,5.8 361.95,11.05 362.45,11.05 362.45,60.05 v1(361.7,60.8) ; LO5.2@323.85,90.17 320.83,90.17 319.7,91.3 319.7,98.8 ; v1(361.7,93.3) 356.2,98.8 319.7,98.8 ; 362.7,11.05 385.45,11.05 387.7,13.3 407.2,13.3 407.67,12.83 LO4.2@407.67,11.43 420.57,11.43 v1(420.7,11.3) ; 105.95,99.3 158.2,99.3 165.2,92.3 169.7,92.3 176.7,99.3 213.2,99.3 ; 213.2,99.3 231.7,99.3 239.2,91.8 276.7,91.8 283.7,98.8 319.7,98.8
  other v1: 288.2,10.8
GND: C5.2 C6.2 C7.2 C11.2 C12.2 C13.2 C14.- C20.- C21.- C22.- C23.- C24.2 C25.2 C26.2 C27.2 C28.2 C31.- C32.- C33.- C34.- C36.2 C37.2 C38.2 C39.2 C41.+ C42.+ C43.+ C44.+ C46.1 C47.1 C48.1 C49.1 C122.2 J10.2 J10.3 J10.4 J10.5 J11.2 J11.3 J11.4 J11.5 J12.2 J12.3 J12.4 J12.5 J13.2 J13.3 J13.4 J13.5 JP1.5 JP1.6 JP1.7 JP1.8 JP2.5 JP2.6 JP2.7 JP2.8 JP3.5 JP3.6 JP3.7 JP3.8 JP4.5 JP4.6 JP4.7 JP4.8 JP5.5 JP5.6 JP5.7 JP5.8 JP6.5 JP6.6 JP6.7 JP6.8 JP7.5 JP7.6 JP7.7 JP7.8 JP8.5 JP8.6 JP8.7 JP8.8 JP10.1 JP11.1 JP40.1 JP40.3 JP40.5 JP40.7 LED1.K LED80.K LED81.K LED82.A LED83.K LO1.1 LO1.4 LO1.6 LO1.7 LO2.1 LO2.4 LO2.6 LO2.7 LO3.1 LO3.4 LO3.6 LO3.7 LO4.1 LO4.4 LO4.6 LO4.7 LO5.1 LO5.4 LO5.6 LO5.7 LO6.1 LO6.4 LO6.6 LO6.7 LO7.1 LO7.4 LO7.6 LO7.7 LO8.1 LO8.4 LO8.6 LO8.7 PS1.2 PS1.3 PS1.6 Q1.2 Q2.2 Q3.2 Q4.2 R20.2 R21.2 R23.2 R24.2 R42.2 R52.2 R59.2 R60.2 R61.2 R63.2 R64.2 R71.2 R73.2 R75.2 R96.2 R97.2 RF1.2 RF1.4 RF3.2 RF3.4 SPLT1.2 SPLT1.7 SPLT1.8 SPLT1.13 SPLT1.14 SPLT2.2 SPLT2.7 SPLT2.8 SPLT2.13 SPLT2.14 VR1.2 VR1.3 VR1.6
